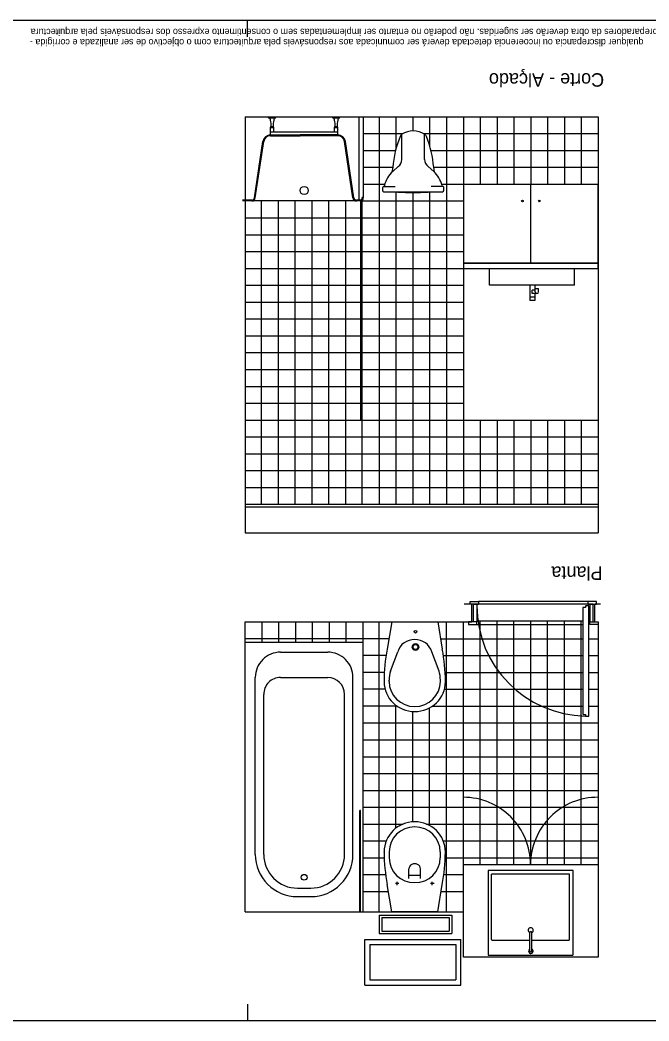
# Model space of a CAD drawing. Extents: x 1283 to 1294.6, y -281.1 to -275.1.
# Drawn here: x 1285.32 to 1289.05, y -281.08 to -275.14 of the extents above; entities that cross this region are included whole.
import ezdxf

# ---------------------------------------------------------------- set-up
doc = ezdxf.new("R2010")
doc.units = 0
for name, color, linetype in [('Level 1', 7, 'Continuous'), ('Level 10', 7, 'Continuous'), ('Level 11', 7, 'Continuous'), ('Level 13', 7, 'Continuous'), ('Level 2', 7, 'Continuous'), ('Level 36', 7, 'Continuous'), ('Level 4', 7, 'Continuous'), ('Level 60', 7, 'Continuous'), ('Level 62', 7, 'Continuous')]:
    doc.layers.add(name, color=color, linetype=linetype)

msp = doc.modelspace()

# ---------------------------------------------------------------- linework, layer by layer
at = {"layer": 'Level 1'}
for p, q in [((1286.6547, -275.712), (1286.6547, -278.182)), ((1286.6547, -275.712), (1288.7497, -275.712)), ((1287.3297, -275.712), (1287.3297, -276.207)), ((1287.3547, -275.712), (1287.3547, -276.192)), ((1288.7497, -275.712), (1288.7497, -278.182)), ((1287.3397, -276.207), (1287.3297, -276.207)), ((1287.3547, -276.192), (1287.3497, -276.192)), ((1287.3497, -276.192), (1287.3497, -276.197)), ((1286.6547, -278.012), (1288.7497, -278.012)), ((1286.6547, -278.027), (1288.7497, -278.027)), ((1286.6547, -278.182), (1288.7497, -278.182)), ((1287.9997, -278.6047), (1287.9547, -278.6047)), ((1287.9997, -278.7097), (1287.9997, -278.6047)), ((1288.7647, -278.6047), (1288.7297, -278.6047)), ((1288.7297, -278.7097), (1288.7297, -278.6047)), ((1286.6547, -278.7097), (1287.9997, -278.7097)), ((1286.6547, -280.4297), (1286.6547, -278.7097)), ((1288.7297, -278.7097), (1288.7497, -278.7097)), ((1288.7497, -278.7097), (1288.7497, -280.6997)), ((1286.6547, -280.4297), (1287.9497, -280.4297)), ((1287.9497, -280.6997), (1287.9497, -280.4297)), ((1287.3647, -280.5947), (1287.9347, -280.5947)), ((1287.3647, -280.8647), (1287.3647, -280.5947)), ((1287.9347, -280.8647), (1287.9347, -280.5947)), ((1287.3947, -280.6247), (1287.9047, -280.6247)), ((1287.3947, -280.6247), (1287.3947, -280.8347)), ((1287.9047, -280.6247), (1287.9047, -280.8347)), ((1288.7497, -280.6997), (1287.9497, -280.6997)), ((1287.3947, -280.8347), (1287.9047, -280.8347)), ((1287.3647, -280.8647), (1287.9347, -280.8647))]:
    msp.add_line(p, q, dxfattribs=at)
msp.add_arc((1287.3397, -276.197), 0.01, 270, 0, dxfattribs=at)
at = {"layer": 'Level 10'}
for p, q in [((1287.4497, -275.712), (1287.4497, -278.012)), ((1287.5497, -275.712), (1287.5497, -275.9019)), ((1287.6497, -275.712), (1287.6497, -275.7967)), ((1287.7497, -275.712), (1287.7497, -275.8845)), ((1287.8497, -275.712), (1287.8497, -278.012)), ((1287.9497, -275.712), (1287.9497, -278.012)), ((1288.0497, -275.712), (1288.0497, -276.112)), ((1288.1497, -275.712), (1288.1497, -276.112)), ((1288.2497, -275.712), (1288.2497, -276.112)), ((1288.3497, -275.712), (1288.3497, -276.112)), ((1288.4497, -275.712), (1288.4497, -276.112)), ((1288.5497, -275.712), (1288.5497, -276.112)), ((1288.6497, -275.712), (1288.6497, -276.112)), ((1287.3547, -275.812), (1287.5908, -275.812)), ((1287.7136, -275.812), (1287.9537, -275.812)), ((1287.9497, -275.812), (1288.7497, -275.812)), ((1287.3547, -275.912), (1287.5471, -275.912)), ((1287.7573, -275.912), (1287.9537, -275.912)), ((1287.9497, -275.912), (1288.7497, -275.912)), ((1287.3547, -276.012), (1287.5305, -276.012)), ((1287.7739, -276.012), (1287.9537, -276.012)), ((1287.9497, -276.012), (1288.7497, -276.012)), ((1287.3547, -276.112), (1287.4835, -276.112)), ((1287.8209, -276.112), (1287.9497, -276.112)), ((1287.5497, -276.1581), (1287.5497, -278.012)), ((1287.6497, -276.162), (1287.6497, -278.012)), ((1287.7497, -276.1585), (1287.7497, -278.012)), ((1286.7497, -276.212), (1286.7497, -278.012)), ((1286.8497, -276.212), (1286.8497, -278.012)), ((1286.9497, -276.212), (1286.9497, -278.012)), ((1287.0497, -276.212), (1287.0497, -278.012)), ((1287.1497, -276.212), (1287.1497, -278.012)), ((1287.2497, -276.212), (1287.2497, -278.012)), ((1287.3447, -276.212), (1287.9497, -276.212)), ((1287.3497, -278.012), (1287.3497, -276.2106)), ((1286.6547, -276.312), (1287.9497, -276.312)), ((1286.6547, -276.412), (1287.9497, -276.412)), ((1286.6547, -276.512), (1287.9497, -276.512)), ((1286.6547, -276.612), (1287.3497, -276.612)), ((1287.3497, -276.612), (1287.9497, -276.612)), ((1286.6547, -276.712), (1287.9497, -276.712)), ((1286.6547, -276.812), (1287.9497, -276.812)), ((1286.6547, -276.912), (1287.9497, -276.912)), ((1286.6547, -277.012), (1287.9497, -277.012)), ((1286.6547, -277.112), (1287.9497, -277.112)), ((1286.6547, -277.212), (1287.9497, -277.212)), ((1286.6547, -277.312), (1287.9497, -277.312)), ((1286.6547, -277.412), (1287.9497, -277.412)), ((1286.6547, -277.512), (1287.9497, -277.512)), ((1288.0497, -277.512), (1288.0497, -278.012)), ((1288.1497, -277.512), (1288.1497, -278.012)), ((1288.2497, -277.512), (1288.2497, -278.012)), ((1288.3497, -277.512), (1288.3497, -278.012)), ((1288.4497, -277.512), (1288.4497, -278.012)), ((1288.5497, -277.512), (1288.5497, -278.012)), ((1288.6497, -277.512), (1288.6497, -278.012)), ((1286.6547, -277.612), (1288.7497, -277.612)), ((1286.6547, -277.712), (1288.7497, -277.712)), ((1286.6547, -277.812), (1288.7497, -277.812)), ((1286.6547, -277.912), (1288.7497, -277.912)), ((1288.7047, -278.6047), (1288.0297, -278.6047)), ((1288.6597, -278.7047), (1288.0297, -278.7047)), ((1288.0497, -280.1497), (1288.0497, -278.7047)), ((1288.1497, -280.1497), (1288.1497, -278.7047)), ((1288.2497, -280.1497), (1288.2497, -278.7047)), ((1288.3497, -280.1497), (1288.3497, -278.7047)), ((1288.4497, -280.1497), (1288.4497, -278.7047)), ((1288.5497, -280.1497), (1288.5497, -278.7047)), ((1288.6497, -280.1497), (1288.6497, -278.7047)), ((1286.7547, -278.8297), (1286.7547, -278.7097)), ((1286.8547, -278.8297), (1286.8547, -278.7097)), ((1286.9547, -278.8297), (1286.9547, -278.7097)), ((1287.0547, -278.8297), (1287.0547, -278.7097)), ((1287.1547, -278.8297), (1287.1547, -278.7097)), ((1287.2547, -278.8297), (1287.2547, -278.7097)), ((1287.4497, -280.4297), (1287.4497, -278.7097)), ((1287.8497, -280.4297), (1287.8497, -278.7097)), ((1287.9497, -280.1497), (1287.9497, -278.7097)), ((1287.5079, -278.8097), (1286.6547, -278.8097)), ((1287.8145, -278.8097), (1288.6597, -278.8097)), ((1288.6947, -278.8097), (1288.7497, -278.8097)), ((1287.491, -278.9097), (1287.3547, -278.9097)), ((1287.8314, -278.9097), (1288.6597, -278.9097)), ((1288.6947, -278.9097), (1288.7497, -278.9097)), ((1287.4805, -279.0097), (1287.3547, -279.0097)), ((1287.8419, -279.0097), (1288.6597, -279.0097)), ((1288.6947, -279.0097), (1288.7497, -279.0097)), ((1287.4852, -279.1097), (1287.3547, -279.1097)), ((1287.8372, -279.1097), (1288.6597, -279.1097)), ((1288.6947, -279.1097), (1288.7497, -279.1097)), ((1287.5567, -279.2097), (1287.3547, -279.2097)), ((1287.5497, -279.9335), (1287.5497, -279.2047)), ((1287.7497, -279.9187), (1287.7497, -279.2194)), ((1287.7657, -279.2097), (1288.6597, -279.2097)), ((1288.6947, -279.2097), (1288.7497, -279.2097)), ((1287.6497, -279.8966), (1287.6497, -279.2415)), ((1287.3547, -279.3097), (1288.7497, -279.3097)), ((1287.3547, -279.4097), (1288.7497, -279.4097)), ((1287.3547, -279.5097), (1288.7497, -279.5097)), ((1287.3547, -279.6097), (1288.7497, -279.6097)), ((1287.3547, -279.7097), (1288.7497, -279.7097)), ((1287.3547, -279.8097), (1288.7497, -279.8097)), ((1287.3547, -279.9097), (1287.5916, -279.9097)), ((1287.7308, -279.9097), (1288.7497, -279.9097)), ((1287.3547, -280.0097), (1287.4916, -280.0097)), ((1287.8308, -280.0097), (1288.7497, -280.0097)), ((1287.3547, -280.1097), (1287.4799, -280.1097)), ((1287.8425, -280.1097), (1288.7497, -280.1097)), ((1287.3547, -280.2097), (1287.4883, -280.2097)), ((1287.8341, -280.2097), (1287.9497, -280.2097)), ((1287.3547, -280.3097), (1287.5048, -280.3097)), ((1287.8176, -280.3097), (1287.9497, -280.3097))]:
    msp.add_line(p, q, dxfattribs=at)
at = {"layer": 'Level 11'}
for p, q in [((1286.794, -275.7119), (1286.8353, -275.7119)), ((1286.794, -275.7186), (1286.794, -275.7119)), ((1286.794, -275.7186), (1286.8353, -275.7186)), ((1286.8353, -275.7186), (1286.8353, -275.7119)), ((1287.1742, -275.7119), (1287.2155, -275.7119)), ((1287.1742, -275.7186), (1287.1742, -275.7119)), ((1287.1742, -275.7186), (1287.2155, -275.7186)), ((1287.2155, -275.7186), (1287.2155, -275.7119)), ((1286.8041, -275.7755), (1286.809, -275.7695)), ((1286.8041, -275.7755), (1286.8251, -275.7755)), ((1286.8041, -275.8019), (1286.8041, -275.7755)), ((1286.809, -275.7695), (1286.8202, -275.7695)), ((1286.8251, -275.7755), (1286.8202, -275.7695)), ((1286.8251, -275.8019), (1286.8251, -275.7755)), ((1287.1843, -275.7755), (1287.1892, -275.7695)), ((1287.1843, -275.7755), (1287.2053, -275.7755)), ((1287.1843, -275.8019), (1287.1843, -275.7755)), ((1287.1892, -275.7695), (1287.2004, -275.7695)), ((1287.2053, -275.7755), (1287.2004, -275.7695)), ((1287.2053, -275.82), (1287.2053, -275.7755)), ((1286.8041, -275.8247), (1286.8041, -275.8019)), ((1286.8041, -275.8019), (1287.2053, -275.8019)), ((1286.8041, -275.82), (1286.9805, -275.82)), ((1286.8041, -275.825), (1286.9805, -275.825)), ((1287.029, -275.82), (1286.9805, -275.82)), ((1287.029, -275.825), (1286.9805, -275.825)), ((1287.2053, -275.82), (1287.029, -275.82)), ((1287.2053, -275.825), (1287.029, -275.825)), ((1287.5847, -275.9668), (1287.5847, -275.8154)), ((1287.7197, -275.9668), (1287.7197, -275.8154)), ((1286.7097, -276.1929), (1286.7596, -275.8583)), ((1286.7147, -276.1936), (1286.7645, -275.8591)), ((1287.2946, -276.1936), (1287.2449, -275.8591)), ((1287.2998, -276.1942), (1287.2498, -275.8583)), ((1287.5305, -276.0121), (1287.5262, -276.0408)), ((1287.5305, -276.0368), (1287.5633, -276.0066)), ((1287.7739, -276.0368), (1287.7411, -276.0066)), ((1287.7782, -276.0408), (1287.7739, -276.0121)), ((1287.4697, -276.1342), (1287.4697, -276.1488)), ((1287.4755, -276.1265), (1287.5448, -276.1265)), ((1287.8289, -276.1265), (1287.7596, -276.1265)), ((1287.8347, -276.1488), (1287.8347, -276.1342)), ((1286.6947, -276.207), (1286.6397, -276.207)), ((1287.3447, -276.207), (1287.3146, -276.207)), ((1287.3547, -276.192), (1287.3497, -276.192)), ((1287.3497, -276.202), (1287.3497, -276.192)), ((1287.3547, -276.202), (1287.3547, -276.192)), ((1286.6947, -276.212), (1286.6397, -276.212)), ((1287.3148, -276.212), (1286.6947, -276.212)), ((1287.3447, -276.212), (1287.3146, -276.212)), ((1288.1042, -276.712), (1288.1042, -276.612)), ((1288.6086, -276.712), (1288.6086, -276.612)), ((1288.3438, -276.712), (1288.3438, -276.802)), ((1288.3738, -276.712), (1288.3738, -276.742)), ((1288.3763, -276.752), (1288.3763, -276.732)), ((1288.3763, -276.732), (1288.3963, -276.732)), ((1288.3963, -276.752), (1288.3963, -276.732)), ((1288.3438, -276.762), (1288.3438, -276.802)), ((1288.3738, -276.782), (1288.3438, -276.782)), ((1288.3738, -276.802), (1288.3438, -276.802)), ((1288.3738, -276.762), (1288.3738, -276.802)), ((1287.5243, -278.7101), (1287.4976, -278.8721)), ((1287.5243, -278.7101), (1287.7981, -278.7101)), ((1287.7981, -278.7101), (1287.8247, -278.8721)), ((1286.6547, -280.4297), (1286.6547, -278.8297)), ((1286.6547, -278.8297), (1287.3547, -278.8297)), ((1286.6547, -280.4297), (1286.6547, -278.8297)), ((1286.6547, -278.8297), (1287.3547, -278.8297)), ((1287.3547, -280.4297), (1287.3547, -278.8297)), ((1287.3547, -280.4297), (1287.3547, -278.8297)), ((1286.8647, -278.8897), (1287.1447, -278.8897)), ((1286.8647, -278.8897), (1287.1447, -278.8897)), ((1287.5168, -279.0013), (1287.5604, -278.8866)), ((1287.8056, -279.0013), (1287.7619, -278.8866)), ((1286.7147, -280.0897), (1286.7147, -279.0397)), ((1286.7147, -280.0897), (1286.7147, -279.0397)), ((1286.8647, -279.0397), (1287.1447, -279.0397)), ((1286.8647, -279.0397), (1287.1447, -279.0397)), ((1287.2947, -280.0897), (1287.2947, -279.0397)), ((1287.2947, -280.0897), (1287.2947, -279.0397)), ((1287.4791, -279.061), (1287.4791, -279.0646)), ((1287.5091, -279.0643), (1287.5091, -279.0562)), ((1287.8133, -279.0643), (1287.8133, -279.0562)), ((1287.8433, -279.061), (1287.8433, -279.0646)), ((1286.7647, -280.0897), (1286.7647, -279.1397)), ((1286.7647, -280.0897), (1286.7647, -279.1397)), ((1287.2447, -280.0897), (1287.2447, -279.1397)), ((1287.2447, -280.0897), (1287.2447, -279.1397)), ((1287.4794, -280.0771), (1287.4794, -280.0734)), ((1287.5094, -280.0737), (1287.5094, -280.1098)), ((1287.8131, -280.0737), (1287.8131, -280.1098)), ((1287.843, -280.0771), (1287.8431, -280.0734)), ((1287.6269, -280.2317), (1287.6269, -280.1745)), ((1287.6956, -280.2317), (1287.6956, -280.1745)), ((1288.0965, -280.1849), (1288.0965, -280.6841)), ((1288.6009, -280.1849), (1288.0965, -280.1849)), ((1288.6009, -280.6841), (1288.6009, -280.1849)), ((1287.6956, -280.214), (1287.6269, -280.214)), ((1288.1176, -280.5945), (1288.1176, -280.206)), ((1288.5798, -280.206), (1288.1176, -280.206)), ((1288.5798, -280.5945), (1288.5798, -280.206)), ((1286.9647, -280.2897), (1287.0447, -280.2897)), ((1286.9647, -280.2897), (1287.0447, -280.2897)), ((1287.5245, -280.4297), (1287.4979, -280.2677)), ((1287.5669, -280.2615), (1287.5469, -280.2615)), ((1287.5569, -280.2715), (1287.5569, -280.2515)), ((1287.7756, -280.2615), (1287.7556, -280.2615)), ((1287.7656, -280.2715), (1287.7656, -280.2515)), ((1287.7979, -280.4297), (1287.8245, -280.2677)), ((1286.9647, -280.3397), (1287.0447, -280.3397)), ((1286.9647, -280.3397), (1287.0447, -280.3397)), ((1286.6547, -280.4297), (1287.3547, -280.4297)), ((1286.6547, -280.4297), (1287.3547, -280.4297)), ((1287.4506, -280.4497), (1287.4506, -280.5597)), ((1287.4506, -280.4497), (1287.8806, -280.4497)), ((1287.4656, -280.4647), (1287.8656, -280.4647)), ((1287.4656, -280.4647), (1287.4656, -280.5447)), ((1287.7979, -280.4297), (1287.5245, -280.4297)), ((1287.8656, -280.4647), (1287.8656, -280.5447)), ((1287.8806, -280.4497), (1287.8806, -280.5597)), ((1287.4656, -280.5447), (1287.8656, -280.5447)), ((1287.4506, -280.5597), (1287.8806, -280.5597)), ((1288.122, -280.5989), (1288.3448, -280.5989)), ((1288.3448, -280.6633), (1288.3448, -280.5538)), ((1288.356, -280.6633), (1288.356, -280.5538)), ((1288.356, -280.5989), (1288.5754, -280.5989)), ((1288.1009, -280.6885), (1288.5965, -280.6885))]:
    msp.add_line(p, q, dxfattribs=at)
msp.add_lwpolyline([(1287.4777, -276.1568), (1287.6547, -276.1568), (1287.8267, -276.1568)], dxfattribs=at)
for centre, radius in [((1287.0047, -276.15), 0.0242), ((1287.6658, -278.7681), 0.00766), ((1287.6658, -278.8589), 0.02), ((1287.6658, -278.8589), 0.0146), ((1287.0047, -280.2253), 0.0173), ((1287.0047, -280.2253), 0.0173)]:
    msp.add_circle(centre, radius, dxfattribs=at)
for centre, radius, start, end in [((1286.7876, -275.7357), 0.0182, 10.7191, 69.4894), ((1286.6093, -275.7695), 0.1997, 0, 10.7194), ((1287.02, -275.7695), 0.1997, 169.2807, 180), ((1286.8417, -275.7357), 0.0182, 110.5111, 169.2809), ((1287.1678, -275.7357), 0.0182, 10.7191, 69.4894), ((1286.9895, -275.7695), 0.1997, 0, 10.7194), ((1287.4002, -275.7695), 0.1997, 169.2807, 180), ((1287.2219, -275.7357), 0.0182, 110.5111, 169.2809), ((1286.8041, -275.865), 0.045, 89.99967, 171.51795), ((1286.8041, -275.865), 0.04, 90.00022, 171.51768), ((1287.2053, -275.865), 0.045, 8.45973, 90.00002), ((1287.2053, -275.865), 0.04, 8.46004, 90.00021), ((1288.1541, -276.0643), 0.6258, 157.87829, 175.22161), ((1287.6051, -275.8421), 0.0336, 127.37509, 156.36146), ((1287.6522, -275.9279), 0.1312, 59.05228, 120.94773), ((1287.6993, -275.8421), 0.0336, 23.63855, 52.62492), ((1287.1503, -276.0643), 0.6258, 4.7784, 22.12172), ((1287.5332, -275.9647), 0.0516, 305.66936, 357.68937), ((1287.7712, -275.9647), 0.0516, 182.31063, 234.33065), ((1287.6442, -276.1602), 0.1678, 132.66339, 166.38286), ((1287.6602, -276.1602), 0.1678, 13.61715, 47.33661), ((1287.4777, -276.1342), 0.008, 106.01353, 180), ((1287.4777, -276.1488), 0.008, 180, 270), ((1287.4733, -276.1188), 0.008, 286.01353, 346.38286), ((1287.8311, -276.1188), 0.008, 193.61715, 253.98648), ((1287.8266, -276.1488), 0.008, 270, 0), ((1287.8266, -276.1342), 0.008, 0, 73.98648), ((1286.6947, -276.192), 0.015, 269.99948, 355.23623), ((1286.6947, -276.192), 0.02, 269.99948, 355.23623), ((1287.3146, -276.192), 0.02, 184.76282, 270.00041), ((1287.3146, -276.192), 0.015, 188.45921, 269.99916), ((1287.3447, -276.202), 0.005, 269.99979, 359.99591), ((1287.3447, -276.202), 0.01, 269.99878, 0.00082), ((1287.6598, -274.5863), 1.5757, 265.34687, 269.6323), ((1287.6456, -274.6022), 1.5598, 270.14848, 274.66454), ((1288.3864, -276.752), 0.01, 180, 0), ((1286.8647, -279.0397), 0.15, 90.00001, 180.00004), ((1286.8647, -279.0397), 0.15, 90.00001, 180.00004), ((1287.1447, -279.0397), 0.15, 359.99983, 90.0001), ((1287.1447, -279.0397), 0.15, 359.99983, 90.0001), ((1287.7091, -279.0562), 0.2, 164.06928, 180.00056), ((1287.6133, -279.0563), 0.2, 0.00165, 15.93186), ((1286.8647, -279.1397), 0.1, 89.99995, 180.00003), ((1286.8647, -279.1397), 0.1, 89.99995, 180.00003), ((1287.1447, -279.1397), 0.1, 0.00013, 89.99986), ((1287.1447, -279.1397), 0.1, 0.00013, 89.99986), ((1286.9647, -280.0897), 0.25, 180.00007, 270.00014), ((1286.9647, -280.0897), 0.25, 180.00007, 270.00014), ((1286.9647, -280.0897), 0.2, 179.99999, 270.00003), ((1286.9647, -280.0897), 0.2, 179.99999, 270.00003), ((1287.0447, -280.0897), 0.25, 269.9999, 0.00001), ((1287.0447, -280.0897), 0.2, 269.99998, 0.00003), ((1287.0447, -280.0897), 0.25, 269.9999, 0.00001), ((1287.0447, -280.0897), 0.2, 269.99998, 0.00003), ((1288.35, -280.5394), 0.015, 293.63069, 249.28331), ((1288.122, -280.5945), 0.00438, 180, 270), ((1288.3504, -280.5532), 0.00566, 354.01756, 185.9962), ((1288.5754, -280.5945), 0.00438, 270, 0), ((1288.3508, -280.6639), 0.0135, 116.71993, 67.39087), ((1288.3504, -280.6639), 0.00566, 174.0038, 5.98244), ((1288.1009, -280.6841), 0.00438, 180, 270), ((1288.5965, -280.6841), 0.00438, 270, 0)]:
    msp.add_arc(centre, radius, start, end, dxfattribs=at)
for centre, major_axis, ratio, start_param, end_param in [((1287.6612, -278.9141), (0.1048, 0), 0.954554, 0.27806, 2.865748), ((1288.8789, -279.061), (-1.3997, 0), 0.831849, 6.120269, 6.283187), ((1286.443, -279.061), (1.4003, 0), 0.831536, 6.283183, 6.446102), ((1287.6612, -279.0644), (0.1821, 0), 0.974849, 3.141596, 6.283183), ((1287.6612, -279.0644), (0.1521, 0), 0.969887, 3.141596, 6.283183), ((1287.6612, -280.0737), (-0.1818, 0), 0.976148, 3.141597, 6.283184), ((1287.6612, -280.0737), (-0.1518, 0), 0.971435, 3.141597, 6.283184), ((1288.8796, -280.0771), (-1.4002, 0), 0.839116, 6.283184, 6.446103), ((1287.6612, -280.1098), (-0.1518, 0), 0.971435, 0.000003, 3.14159), ((1286.4433, -280.0771), (1.3998, 0), 0.839409, 6.120269, 6.283188), ((1287.6612, -280.1747), (-0.0343, 0), 0.873689, 3.141584, 6.283207)]:
    msp.add_ellipse(centre, major_axis=major_axis, ratio=ratio, start_param=start_param, end_param=end_param, dxfattribs=at)
at = {"layer": 'Level 13'}
for p, q in [((1287.9497, -276.112), (1287.9497, -276.612)), ((1287.9497, -276.112), (1288.7477, -276.112)), ((1288.3507, -276.58), (1288.3507, -276.112)), ((1288.7477, -276.112), (1288.7477, -276.612)), ((1287.9497, -276.58), (1288.7477, -276.58)), ((1287.9497, -276.582), (1288.7477, -276.582)), ((1287.9497, -276.612), (1288.7477, -276.612)), ((1288.6086, -276.712), (1288.1042, -276.712)), ((1287.9897, -278.5897), (1288.0397, -278.5897)), ((1287.9897, -278.6047), (1287.9897, -278.5897)), ((1288.0397, -278.6047), (1287.9897, -278.6047)), ((1288.0097, -278.7097), (1288.0097, -278.6047)), ((1288.0097, -278.6047), (1288.0397, -278.6047)), ((1288.0297, -278.6047), (1288.0297, -278.7097)), ((1288.0397, -278.5897), (1288.0397, -278.6047)), ((1288.6597, -278.624), (1288.6597, -279.259)), ((1288.6747, -278.624), (1288.6597, -278.624)), ((1288.6947, -278.614), (1288.6747, -278.614)), ((1288.6747, -278.614), (1288.6747, -278.624)), ((1288.7397, -278.5897), (1288.6897, -278.5897)), ((1288.6897, -278.5897), (1288.6897, -278.6047)), ((1288.7197, -278.6047), (1288.6897, -278.6047)), ((1288.6897, -278.6047), (1288.7397, -278.6047)), ((1288.6947, -279.269), (1288.6947, -278.614)), ((1288.6997, -278.6047), (1288.6997, -278.7097)), ((1288.7197, -278.7097), (1288.7197, -278.6047)), ((1288.7397, -278.6047), (1288.7397, -278.5897)), ((1287.9797, -278.7097), (1287.9797, -278.7247)), ((1288.0297, -278.7097), (1287.9797, -278.7097)), ((1287.9797, -278.7247), (1288.0297, -278.7247)), ((1288.0297, -278.7097), (1288.0097, -278.7097)), ((1288.0297, -278.7247), (1288.0297, -278.7097)), ((1288.6997, -278.7247), (1288.6997, -278.7097)), ((1288.6997, -278.7097), (1288.7197, -278.7097)), ((1288.6997, -278.7097), (1288.7497, -278.7097)), ((1288.7497, -278.7247), (1288.6997, -278.7247)), ((1288.6597, -279.259), (1288.6747, -279.259)), ((1288.6747, -279.259), (1288.6747, -279.2687)), ((1288.6747, -279.269), (1288.6947, -279.269))]:
    msp.add_line(p, q, dxfattribs=at)
for centre in [(1288.3007, -276.212), (1288.4007, -276.212)]:
    msp.add_circle(centre, 0.005, dxfattribs=at)
at = {"layer": 'Level 2'}
for p, q in [((1287.9497, -275.712), (1287.9497, -277.512)), ((1288.3588, -276.762), (1288.3588, -276.742)), ((1288.3763, -276.742), (1288.3588, -276.742)), ((1288.3863, -276.762), (1288.3588, -276.762)), ((1287.9497, -277.512), (1288.7497, -277.512)), ((1287.3547, -278.8297), (1287.3547, -278.7097)), ((1287.3547, -278.8297), (1287.3547, -278.7097)), ((1287.9497, -280.6977), (1287.9497, -280.1497)), ((1287.9497, -280.1497), (1288.7477, -280.1497))]:
    msp.add_line(p, q, dxfattribs=at)
at = {"layer": 'Level 36'}
for p, q in [((1287.3397, -276.212), (1287.3397, -277.512)), ((1287.3447, -276.212), (1287.3447, -277.512)), ((1287.3347, -280.4297), (1287.3347, -279.8297)), ((1287.3397, -279.8297), (1287.3347, -279.8297)), ((1287.3397, -280.4297), (1287.3397, -279.8297))]:
    msp.add_line(p, q, dxfattribs=at)
at = {"layer": 'Level 4'}
for p, q in [((1288.6897, -278.5897), (1288.0397, -278.5897)), ((1288.0297, -278.7247), (1288.6597, -278.7247)), ((1287.9497, -280.1497), (1287.9497, -279.7507))]:
    msp.add_line(p, q, dxfattribs=at)
for centre, start, end in [((1287.9497, -280.1497), 0, 90.00107), ((1288.7477, -280.1497), 89.71326, 180)]:
    msp.add_arc(centre, 0.399, start, end, dxfattribs=at)
msp.add_ellipse((1288.6884, -278.614), major_axis=(0.6586, 0), ratio=0.994279, start_param=3.141593, end_param=4.691673, dxfattribs=at)
at = {"layer": 'Level 62'}
for p, q in [((1286.6675, -275.2381), (1286.6675, -275.1381)), ((1286.6675, -280.9781), (1286.6675, -281.0781))]:
    msp.add_line(p, q, dxfattribs=at)
msp.add_lwpolyline([(1294.5671, -275.1381), (1294.5671, -281.0781), (1282.9675, -281.0781), (1282.9675, -275.1381)], close=True, dxfattribs=at)

# ---------------------------------------------------------------- texts
at = {"layer": 'Level 60'}
for s, p in [('Corte - Alçado', (1288.7854, -275.4536)), ('Planta', (1288.7759, -278.3809))]:
    msp.add_text(s, height=0.08, rotation=180.00001, dxfattribs=at).set_placement(p)
at = {"layer": 'Level 62'}
for s, p in [('cutantes e preparadores da obra deverão ser sugeridas. não poderão no entanto ser implementadas sem o consentimento expresso dos responsáveis pela arquitectura', (1289.3655, -275.1902)), ('qualquer discrepancia ou incoerencia detectada deverá ser comunicada aos responsáveis pela arquitectura com o objectivo de ser analizada e corrigida -', (1289.0189, -275.2512))]:
    msp.add_text(s, height=0.0399996, rotation=180, dxfattribs=at).set_placement(p)

doc.saveas('drawing.dxf')
